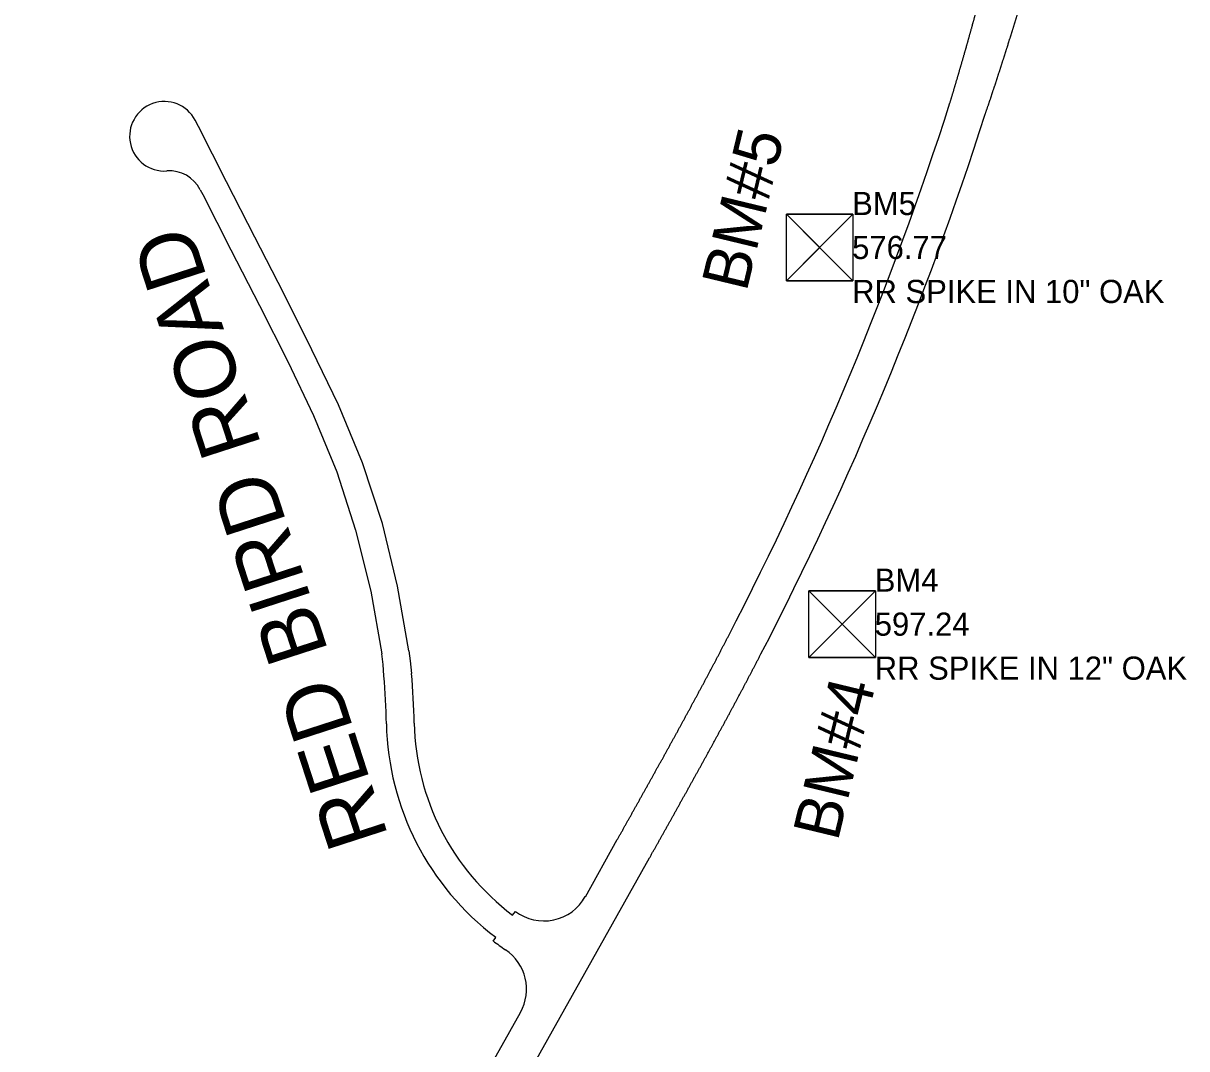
# Model space of a CAD drawing. Extents: x 1649669 to 1659218, y 588594 to 607900.
# Drawn here: x 1654142 to 1655146, y 599457 to 600342 of the extents above; entities that cross this region are included whole.
import ezdxf

# ---------------------------------------------------------------- set-up
doc = ezdxf.new("R2010")
doc.units = 0
for name, color, linetype in [('CTL Bench Mark CELL', 7, 'Continuous'), ('CTL Bench Mark Cogo Comment', 7, 'Continuous'), ('CTL Bench Mark Cogo Elevation', 7, 'Continuous'), ('CTL Bench Mark Cogo Number', 7, 'Continuous'), ('CTL Bench Mark Text', 7, 'Continuous'), ('Exist Roads EOP', 7, 'Continuous'), ('Sheet Data Field CELL', 7, 'Continuous')]:
    doc.layers.add(name, color=color, linetype=linetype)

msp = doc.modelspace()

# ---------------------------------------------------------------- linework, layer by layer
at = {"layer": 'CTL Bench Mark CELL'}
for p, q in [((1654829.6, 600148.6), (1654829.6, 600148.6)), ((1654849.1, 599823.3), (1654849.1, 599823.3))]:
    msp.add_line(p, q, dxfattribs=at)
for points in [[(1654800.8, 600177.3), (1654858.3, 600177.3), (1654858.3, 600119.8), (1654800.8, 600119.8)], [(1654820.3, 599852), (1654877.8, 599852), (1654877.8, 599794.5), (1654820.3, 599794.5)]]:
    msp.add_lwpolyline(points, close=True, dxfattribs=at)
for points in [[(1654858.3, 600177.3), (1654800.8, 600119.8), (1654829.5, 600148.6), (1654858.3, 600119.8), (1654800.8, 600177.3)], [(1654829.5, 600148.6), (1654858.3, 600177.3), (1654800.8, 600177.3), (1654829.5, 600148.6)], [(1654829.5, 600148.6), (1654800.8, 600119.8), (1654858.3, 600119.8), (1654829.5, 600148.6)], [(1654877.8, 599852), (1654820.3, 599794.5), (1654849, 599823.2), (1654877.8, 599794.5), (1654820.3, 599852)], [(1654849, 599823.2), (1654877.8, 599852), (1654820.3, 599852), (1654849, 599823.2)], [(1654849, 599823.2), (1654820.3, 599794.5), (1654877.8, 599794.5), (1654849, 599823.2)]]:
    msp.add_lwpolyline(points, dxfattribs=at)
at = {"layer": 'Exist Roads EOP'}
for p, q in [((1654342.1, 600157.6), (1654317.6, 600205.2)), ((1654367, 600108.9), (1654342.1, 600157.6)), ((1654321.2, 600146.6), (1654345.9, 600098.4)), ((1654391.1, 600060.3), (1654367, 600108.9)), ((1654345.9, 600098.4), (1654370.4, 600050)), ((1654414.3, 600012.6), (1654391.1, 600060.3)), ((1654370.4, 600050), (1654392.6, 600003.4)), ((1654434.9, 599962.7), (1654414.3, 600012.6)), ((1654392.6, 600003.4), (1654412.7, 599954.8)), ((1654452.2, 599910.3), (1654434.9, 599962.7)), ((1654412.7, 599954.8), (1654428.8, 599904.5)), ((1654465.2, 599856.2), (1654452.2, 599910.3)), ((1654428.8, 599904.5), (1654442.1, 599851.9)), ((1654442.1, 599851.9), (1654451.7, 599797.6)), ((1654474.8, 599800.2), (1654465.2, 599856.2)), ((1654627.3, 599587.9), (1654654.9, 599637.2)), ((1654170, 598706.6), (1654682.8, 599621.6)), ((1654564.5, 599572), (1654566.9, 599575.2)), ((1654547.6, 599549.6), (1654550, 599552.8)), ((1654142.1, 598722.2), (1654571.2, 599488))]:
    msp.add_line(p, q, dxfattribs=at)
for points in [[(1654317.6, 600205.2), (1654293.3, 600253), (1654290.5, 600258.5)], [(1654294.8, 600198.5), (1654297, 600194.3), (1654321.2, 600146.6)], [(1654474.8, 599800.2), (1654476, 599791.5), (1654477.3, 599780.7)], [(1654453.3, 599778.7), (1654452.8, 599788.5), (1654451.7, 599797.6)]]:
    msp.add_lwpolyline(points, dxfattribs=at)
for centre, radius, start, end in [((1654263.9, 600244.6), 30, 27.5489, 274.0341), ((1652100.2, 601183.5), 2984, 332.6431, 342.2421), ((1652100.2, 601183.5), 3016, 332.6431, 342.2421), ((1654268.2, 600184.8), 30, 27.1756, 94.0341), ((1653792.7, 599723.3), 663, 1.2083, 4.7972), ((1653792.7, 599723.3), 687, 1.2083, 4.7972), ((1654692.5, 599742.3), 213, 181.2083, 233.0607), ((1654692.5, 599742.3), 237, 181.2083, 233.0607), ((1654591.5, 599608), 41, 233.0607, 330.7332), ((1654692.5, 599742.3), 241, 233.0607, 236.1712), ((1654535.5, 599508), 41, 330.7332, 56.1712)]:
    msp.add_arc(centre, radius, start, end, dxfattribs=at)
for points in [[(1654961.9, 600342.2), (1654962.1, 600343.2), (1654962.4, 600344.1), (1654962.7, 600345), (1654962.9, 600346), (1654963.2, 600346.9), (1654963.4, 600347.8), (1654963.7, 600348.8), (1654963.9, 600349.7), (1654964.2, 600350.6), (1654964.4, 600351.6), (1654964.7, 600352.5), (1654965, 600353.4), (1654965.2, 600354.4), (1654965.5, 600355.3), (1654965.7, 600356.2), (1654966, 600357.2), (1654966.2, 600358.1), (1654966.5, 600359), (1654966.7, 600360), (1654967, 600360.9), (1654967.2, 600361.8), (1654967.5, 600362.8), (1654967.7, 600363.7), (1654968, 600364.6), (1654968.2, 600365.6), (1654968.5, 600366.5), (1654968.7, 600367.4), (1654969, 600368.4), (1654969.2, 600369.3), (1654969.5, 600370.2), (1654969.7, 600371.2), (1654970, 600372.1), (1654970.2, 600373), (1654970.5, 600374), (1654970.7, 600374.9), (1654971, 600375.8), (1654971.2, 600376.8), (1654971.4, 600377.7), (1654971.7, 600378.7), (1654971.9, 600379.6), (1654972.2, 600380.5), (1654972.4, 600381.5), (1654972.7, 600382.4), (1654972.9, 600383.3), (1654973.2, 600384.3), (1654973.4, 600385.2), (1654973.6, 600386.1), (1654973.9, 600387.1), (1654974.1, 600388), (1654974.4, 600389), (1654974.6, 600389.9), (1654974.9, 600390.8), (1654975.1, 600391.8), (1654975.3, 600392.7), (1654975.6, 600393.6), (1654975.8, 600394.6), (1654976.1, 600395.5), (1654976.3, 600396.4), (1654976.5, 600397.4), (1654976.8, 600398.3), (1654977, 600399.3), (1654977.3, 600400.2), (1654977.5, 600401.1), (1654977.7, 600402.1), (1654978, 600403), (1654978.2, 600403.9), (1654978.4, 600404.9), (1654978.7, 600405.8), (1654978.9, 600406.8), (1654979.2, 600407.7), (1654979.4, 600408.6), (1654979.6, 600409.6), (1654979.9, 600410.5), (1654980.1, 600411.4)], [(1654994.9, 600332.5), (1654995.2, 600333.5), (1654995.5, 600334.4), (1654995.8, 600335.3), (1654996.1, 600336.3), (1654996.3, 600337.2), (1654996.6, 600338.1), (1654996.9, 600339.1), (1654997.2, 600340), (1654997.5, 600340.9), (1654997.8, 600341.9), (1654998.1, 600342.8), (1654998.4, 600343.7), (1654998.7, 600344.7), (1654998.9, 600345.6), (1654999.2, 600346.6), (1654999.5, 600347.5), (1654999.8, 600348.4), (1655000.1, 600349.4), (1655000.4, 600350.3), (1655000.7, 600351.2), (1655000.9, 600352.2), (1655001.2, 600353.1), (1655001.5, 600354), (1655001.8, 600355), (1655002.1, 600355.9), (1655002.4, 600356.9), (1655002.7, 600357.8), (1655002.9, 600358.7), (1655003.2, 600359.7), (1655003.5, 600360.6), (1655003.8, 600361.5), (1655004.1, 600362.5), (1655004.3, 600363.4), (1655004.6, 600364.3), (1655004.9, 600365.3), (1655005.2, 600366.2), (1655005.5, 600367.2), (1655005.8, 600368.1), (1655006, 600369), (1655006.3, 600370), (1655006.6, 600370.9), (1655006.9, 600371.9), (1655007.2, 600372.8), (1655007.4, 600373.7), (1655007.7, 600374.7), (1655008, 600375.6), (1655008.3, 600376.5), (1655008.5, 600377.5), (1655008.8, 600378.4), (1655009.1, 600379.4), (1655009.4, 600380.3), (1655009.6, 600381.2), (1655009.9, 600382.2), (1655010.2, 600383.1), (1655010.5, 600384.1), (1655010.7, 600385), (1655011, 600385.9), (1655011.3, 600386.9), (1655011.6, 600387.8), (1655011.8, 600388.8), (1655012.1, 600389.7), (1655012.4, 600390.6), (1655012.7, 600391.6), (1655012.9, 600392.5), (1655013.2, 600393.5), (1655013.5, 600394.4), (1655013.7, 600395.3), (1655014, 600396.3), (1655014.3, 600397.2), (1655014.6, 600398.2), (1655014.8, 600399.1), (1655015.1, 600400), (1655015.4, 600401), (1655015.6, 600401.9)], [(1654942, 600273.4), (1654942.3, 600274.4), (1654942.6, 600275.3), (1654942.9, 600276.2), (1654943.1, 600277.1), (1654943.4, 600278.1), (1654943.7, 600279), (1654944, 600279.9), (1654944.2, 600280.8), (1654944.5, 600281.8), (1654944.8, 600282.7), (1654945.1, 600283.6), (1654945.4, 600284.6), (1654945.6, 600285.5), (1654945.9, 600286.4), (1654946.2, 600287.3), (1654946.5, 600288.3), (1654946.7, 600289.2), (1654947, 600290.1), (1654947.3, 600291), (1654947.5, 600292), (1654947.8, 600292.9), (1654948.1, 600293.8), (1654948.4, 600294.8), (1654948.6, 600295.7), (1654948.9, 600296.6), (1654949.2, 600297.5), (1654949.5, 600298.5), (1654949.7, 600299.4), (1654950, 600300.3), (1654950.3, 600301.3), (1654950.5, 600302.2), (1654950.8, 600303.1), (1654951.1, 600304), (1654951.4, 600305), (1654951.6, 600305.9), (1654951.9, 600306.8), (1654952.2, 600307.8), (1654952.4, 600308.7), (1654952.7, 600309.6), (1654953, 600310.6), (1654953.2, 600311.5), (1654953.5, 600312.4), (1654953.8, 600313.3), (1654954, 600314.3), (1654954.3, 600315.2), (1654954.6, 600316.1), (1654954.8, 600317.1), (1654955.1, 600318), (1654955.4, 600318.9), (1654955.6, 600319.9), (1654955.9, 600320.8), (1654956.2, 600321.7), (1654956.4, 600322.7), (1654956.7, 600323.6), (1654956.9, 600324.5), (1654957.2, 600325.4), (1654957.5, 600326.4), (1654957.7, 600327.3), (1654958, 600328.2), (1654958.3, 600329.2), (1654958.5, 600330.1), (1654958.8, 600331), (1654959, 600332), (1654959.3, 600332.9), (1654959.6, 600333.8), (1654959.8, 600334.8), (1654960.1, 600335.7), (1654960.3, 600336.6), (1654960.6, 600337.6), (1654960.9, 600338.5), (1654961.1, 600339.4), (1654961.4, 600340.4), (1654961.6, 600341.3), (1654961.9, 600342.2)], [(1654972.5, 600263.7), (1654972.8, 600264.6), (1654973.1, 600265.5), (1654973.4, 600266.4), (1654973.7, 600267.4), (1654974.1, 600268.3), (1654974.4, 600269.2), (1654974.7, 600270.2), (1654975, 600271.1), (1654975.3, 600272), (1654975.6, 600272.9), (1654975.9, 600273.9), (1654976.2, 600274.8), (1654976.5, 600275.7), (1654976.9, 600276.6), (1654977.2, 600277.6), (1654977.5, 600278.5), (1654977.8, 600279.4), (1654978.1, 600280.4), (1654978.4, 600281.3), (1654978.7, 600282.2), (1654979, 600283.1), (1654979.3, 600284.1), (1654979.6, 600285), (1654979.9, 600285.9), (1654980.2, 600286.9), (1654980.5, 600287.8), (1654980.9, 600288.7), (1654981.2, 600289.7), (1654981.5, 600290.6), (1654981.8, 600291.5), (1654982.1, 600292.4), (1654982.4, 600293.4), (1654982.7, 600294.3), (1654983, 600295.2), (1654983.3, 600296.2), (1654983.6, 600297.1), (1654983.9, 600298), (1654984.2, 600299), (1654984.5, 600299.9), (1654984.8, 600300.8), (1654985.1, 600301.7), (1654985.4, 600302.7), (1654985.7, 600303.6), (1654986, 600304.5), (1654986.3, 600305.5), (1654986.6, 600306.4), (1654986.9, 600307.3), (1654987.2, 600308.3), (1654987.5, 600309.2), (1654987.8, 600310.1), (1654988.1, 600311.1), (1654988.4, 600312), (1654988.7, 600312.9), (1654989, 600313.9), (1654989.3, 600314.8), (1654989.6, 600315.7), (1654989.9, 600316.7), (1654990.2, 600317.6), (1654990.5, 600318.5), (1654990.8, 600319.5), (1654991.1, 600320.4), (1654991.4, 600321.3), (1654991.7, 600322.3), (1654992, 600323.2), (1654992.3, 600324.1), (1654992.5, 600325.1), (1654992.8, 600326), (1654993.1, 600326.9), (1654993.4, 600327.9), (1654993.7, 600328.8), (1654994, 600329.7), (1654994.3, 600330.7), (1654994.6, 600331.6), (1654994.9, 600332.5)], [(1654654.9, 599637.2), (1654656.2, 599639.6), (1654657.5, 599641.9), (1654658.9, 599644.3), (1654660.2, 599646.7), (1654661.5, 599649), (1654662.8, 599651.4), (1654664.1, 599653.7), (1654665.5, 599656.1), (1654666.8, 599658.4), (1654668.1, 599660.8), (1654669.4, 599663.1), (1654670.7, 599665.5), (1654672, 599667.9), (1654673.4, 599670.2), (1654674.7, 599672.6), (1654676, 599674.9), (1654677.3, 599677.3), (1654678.6, 599679.6), (1654679.9, 599682), (1654681.3, 599684.4), (1654682.6, 599686.7), (1654683.9, 599689.1), (1654685.2, 599691.4), (1654686.5, 599693.8), (1654687.8, 599696.2), (1654689.1, 599698.5), (1654690.4, 599700.9), (1654691.7, 599703.2), (1654693.1, 599705.6), (1654694.4, 599707.9), (1654695.7, 599710.3), (1654697, 599712.7), (1654698.3, 599715), (1654699.6, 599717.4), (1654700.9, 599719.8), (1654702.2, 599722.1), (1654703.5, 599724.5), (1654704.8, 599726.8), (1654706.1, 599729.2), (1654707.4, 599731.6), (1654708.7, 599733.9), (1654709.9, 599736.3), (1654711.2, 599738.7), (1654712.5, 599741), (1654713.8, 599743.4), (1654715.1, 599745.8), (1654716.4, 599748.1), (1654717.7, 599750.5), (1654719, 599752.9), (1654720.2, 599755.2), (1654721.5, 599757.6), (1654722.8, 599760), (1654724.1, 599762.3), (1654725.3, 599764.7), (1654726.6, 599767.1), (1654727.9, 599769.5), (1654729.2, 599771.8), (1654730.4, 599774.2), (1654731.7, 599776.6), (1654733, 599778.9), (1654734.2, 599781.3), (1654735.5, 599783.7), (1654736.7, 599786.1), (1654738, 599788.5), (1654739.3, 599790.8), (1654740.5, 599793.2), (1654741.8, 599795.6), (1654743, 599798), (1654744.3, 599800.4), (1654745.5, 599802.7), (1654746.7, 599805.1), (1654748, 599807.5), (1654749.2, 599809.9), (1654750.5, 599812.3)], [(1654682.8, 599621.6), (1654684.1, 599623.9), (1654685.4, 599626.3), (1654686.8, 599628.7), (1654688.1, 599631), (1654689.4, 599633.4), (1654690.7, 599635.7), (1654692.1, 599638.1), (1654693.4, 599640.4), (1654694.7, 599642.8), (1654696, 599645.2), (1654697.3, 599647.5), (1654698.7, 599649.9), (1654700, 599652.2), (1654701.3, 599654.6), (1654702.6, 599657), (1654703.9, 599659.3), (1654705.3, 599661.7), (1654706.6, 599664.1), (1654707.9, 599666.4), (1654709.2, 599668.8), (1654710.5, 599671.2), (1654711.8, 599673.5), (1654713.2, 599675.9), (1654714.5, 599678.2), (1654715.8, 599680.6), (1654717.1, 599683), (1654718.4, 599685.3), (1654719.7, 599687.7), (1654721, 599690.1), (1654722.4, 599692.5), (1654723.7, 599694.8), (1654725, 599697.2), (1654726.3, 599699.6), (1654727.6, 599701.9), (1654728.9, 599704.3), (1654730.2, 599706.7), (1654731.5, 599709.1), (1654732.8, 599711.4), (1654734.1, 599713.8), (1654735.4, 599716.2), (1654736.7, 599718.6), (1654738, 599720.9), (1654739.3, 599723.3), (1654740.6, 599725.7), (1654741.9, 599728.1), (1654743.2, 599730.5), (1654744.5, 599732.9), (1654745.8, 599735.2), (1654747.1, 599737.6), (1654748.4, 599740), (1654749.7, 599742.4), (1654751, 599744.8), (1654752.3, 599747.2), (1654753.5, 599749.6), (1654754.8, 599752), (1654756.1, 599754.3), (1654757.4, 599756.7), (1654758.7, 599759.1), (1654759.9, 599761.5), (1654761.2, 599763.9), (1654762.5, 599766.3), (1654763.8, 599768.7), (1654765, 599771.1), (1654766.3, 599773.5), (1654767.6, 599775.9), (1654768.8, 599778.3), (1654770.1, 599780.7), (1654771.4, 599783.1), (1654772.6, 599785.5), (1654773.9, 599787.9), (1654775.1, 599790.3), (1654776.4, 599792.8), (1654777.6, 599795.2), (1654778.9, 599797.6)]]:
    msp.add_spline(points, degree=3, dxfattribs=at)

# ---------------------------------------------------------------- texts
at = {"layer": 'CTL Bench Mark Cogo Comment'}
for s, p in [('RR SPIKE IN 10" OAK', (1654857.6, 600100.6)), ('RR SPIKE IN 12" OAK', (1654877.1, 599775.3))]:
    msp.add_text(s, height=20, dxfattribs=at).set_placement(p)
at = {"layer": 'CTL Bench Mark Cogo Elevation'}
for s, p in [('576.77', (1654857.6, 600138.6)), ('597.24', (1654877.1, 599813.3))]:
    msp.add_text(s, height=20, dxfattribs=at).set_placement(p)
at = {"layer": 'CTL Bench Mark Cogo Number'}
for s, p in [('BM5', (1654857.6, 600176.6)), ('BM4', (1654877.1, 599851.3))]:
    msp.add_text(s, height=20, dxfattribs=at).set_placement(p)
at = {"layer": 'CTL Bench Mark Text'}
for s, p in [('BM#5', (1654766.3, 600109.4)), ('BM#4', (1654845.1, 599634.9))]:
    msp.add_text(s, height=40, rotation=76.4261, dxfattribs=at).set_placement(p)
at = {"layer": 'Sheet Data Field CELL'}
msp.add_text('RED BIRD ROAD', height=52.501, rotation=107.9755, dxfattribs=at).set_placement((1654457.5, 599639.9))

doc.saveas('drawing.dxf')
